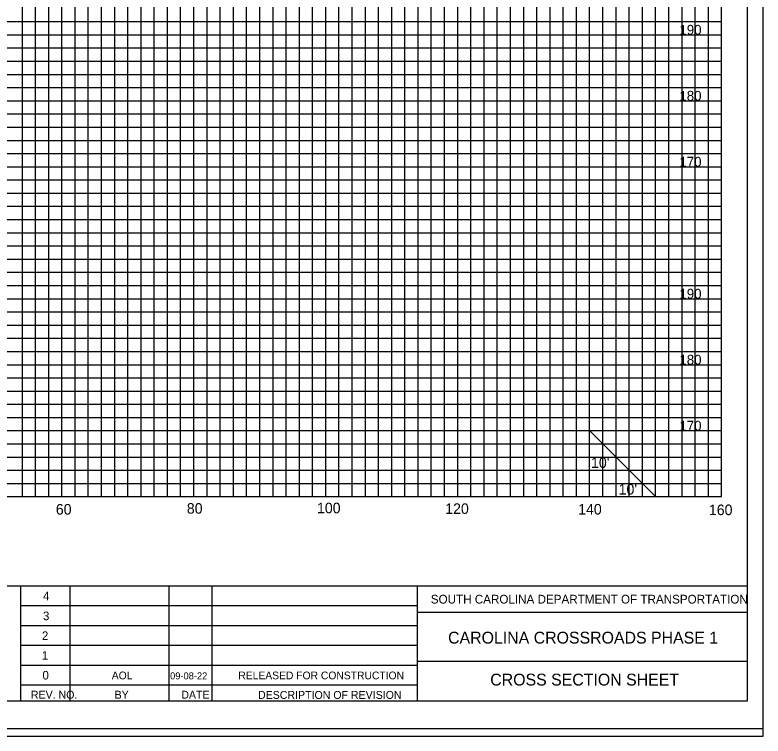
# Model space of a CAD drawing. Extents: x 967 to 1623, y 964 to 7064.
# Drawn here: x 1212.9 to 1326.3, y 963.7 to 1073 of the extents above; entities that cross this region are included whole.
import ezdxf

# ---------------------------------------------------------------- set-up
doc = ezdxf.new("R2010")
doc.units = 0
for name, color, linetype in [('Default', 7, 'Continuous'), ('RD_SHT_Bndy', 7, 'Continuous'), ('RD_SHT_IplotShp', 7, 'Continuous'), ('RD_SHT_Misc1', 7, 'Continuous'), ('RD_SHT_MjGrid', 7, 'Continuous'), ('RD_SHT_MnGrid', 7, 'Continuous'), ('RD_SHT_TX', 7, 'Continuous'), ('RD_Sketch1', 7, 'Continuous')]:
    doc.layers.add(name, color=color, linetype=linetype)

msp = doc.modelspace()

# ---------------------------------------------------------------- linework, layer by layer
at = {"layer": 'RD_SHT_Bndy'}
for p, q in [((1323.89, 1178.46), (1323.89, 968.98)), ((996.11, 986.49), (1323.89, 986.49)), ((1213.76, 968.94), (1213.76, 986.49)), ((1221.26, 968.95), (1221.26, 986.48)), ((1236.26, 968.95), (1236.26, 986.48)), ((1242.76, 968.95), (1242.76, 986.48)), ((1273.88, 968.98), (1273.88, 986.49)), ((1213.76, 983.48), (1273.88, 983.48)), ((1323.93, 982.43), (1273.88, 982.43)), ((1213.76, 980.48), (1273.88, 980.48)), ((1213.76, 977.48), (1273.88, 977.48)), ((1213.76, 974.48), (1273.88, 974.48)), ((1323.89, 975.04), (1273.88, 975.04)), ((1213.76, 971.48), (1273.88, 971.48)), ((1323.89, 968.98), (996.11, 968.98))]:
    msp.add_line(p, q, dxfattribs=at)
at = {"layer": 'RD_SHT_IplotShp'}
for points in [[(967.41, 963.72), (1326.28, 963.72), (1326.28, 1183.72), (967.41, 1183.72)], [(988.52, 964.84), (1326.28, 964.84), (1326.28, 1182.6), (988.52, 1182.6)]]:
    msp.add_lwpolyline(points, close=True, dxfattribs=at)
at = {"layer": 'RD_SHT_MjGrid'}
for p, q in [((1220, 1000), (1220, 1170)), ((1230, 1000), (1230, 1170)), ((1240, 1000), (1240, 1170)), ((1250, 1000), (1250, 1170)), ((1260, 1000), (1260, 1170)), ((1270, 1000), (1270, 1170)), ((1280, 1000), (1280, 1170)), ((1290, 1000), (1290, 1170)), ((1300, 1000), (1300, 1170)), ((1310, 1000), (1310, 1170)), ((1320, 1000), (1320, 1170)), ((1000, 1070), (1320, 1070)), ((1000, 1060), (1320, 1060)), ((1000, 1050), (1320, 1050)), ((1000, 1040), (1320, 1040)), ((1000, 1030), (1320, 1030)), ((1000, 1020), (1320, 1020)), ((1000, 1010), (1320, 1010)), ((1000, 1000), (1320, 1000))]:
    msp.add_line(p, q, dxfattribs=at)
at = {"layer": 'RD_SHT_MnGrid'}
for p, q in [((1214, 1000), (1214, 1170)), ((1216, 1000), (1216, 1170)), ((1218, 1000), (1218, 1170)), ((1222, 1000), (1222, 1170)), ((1224, 1000), (1224, 1170)), ((1226, 1000), (1226, 1170)), ((1228, 1000), (1228, 1170)), ((1232, 1000), (1232, 1170)), ((1234, 1000), (1234, 1170)), ((1236, 1000), (1236, 1170)), ((1238, 1000), (1238, 1170)), ((1242, 1000), (1242, 1170)), ((1244, 1000), (1244, 1170)), ((1246, 1000), (1246, 1170)), ((1248, 1000), (1248, 1170)), ((1252, 1000), (1252, 1170)), ((1254, 1000), (1254, 1170)), ((1256, 1000), (1256, 1170)), ((1258, 1000), (1258, 1170)), ((1262, 1000), (1262, 1170)), ((1264, 1000), (1264, 1170)), ((1266, 1000), (1266, 1170)), ((1268, 1000), (1268, 1170)), ((1272, 1000), (1272, 1170)), ((1274, 1000), (1274, 1170)), ((1276, 1000), (1276, 1170)), ((1278, 1000), (1278, 1170)), ((1282, 1000), (1282, 1170)), ((1284, 1000), (1284, 1170)), ((1286, 1000), (1286, 1170)), ((1288, 1000), (1288, 1170)), ((1292, 1000), (1292, 1170)), ((1294, 1000), (1294, 1170)), ((1296, 1000), (1296, 1170)), ((1298, 1000), (1298, 1170)), ((1302, 1000), (1302, 1170)), ((1304, 1000), (1304, 1170)), ((1306, 1000), (1306, 1170)), ((1308, 1000), (1308, 1170)), ((1312, 1000), (1312, 1170)), ((1314, 1000), (1314, 1170)), ((1316, 1000), (1316, 1170)), ((1318, 1000), (1318, 1170)), ((1000, 1072), (1320, 1072)), ((1000, 1068), (1320, 1068)), ((1000, 1066), (1320, 1066)), ((1000, 1064), (1320, 1064)), ((1000, 1062), (1320, 1062)), ((1000, 1058), (1320, 1058)), ((1000, 1056), (1320, 1056)), ((1000, 1054), (1320, 1054)), ((1000, 1052), (1320, 1052)), ((1000, 1048), (1320, 1048)), ((1000, 1046), (1320, 1046)), ((1000, 1044), (1320, 1044)), ((1000, 1042), (1320, 1042)), ((1000, 1038), (1320, 1038)), ((1000, 1036), (1320, 1036)), ((1000, 1034), (1320, 1034)), ((1000, 1032), (1320, 1032)), ((1000, 1028), (1320, 1028)), ((1000, 1026), (1320, 1026)), ((1000, 1024), (1320, 1024)), ((1000, 1022), (1320, 1022)), ((1000, 1018), (1320, 1018)), ((1000, 1016), (1320, 1016)), ((1000, 1014), (1320, 1014)), ((1000, 1012), (1320, 1012)), ((1000, 1008), (1320, 1008)), ((1000, 1006), (1320, 1006)), ((1000, 1004), (1320, 1004)), ((1000, 1002), (1320, 1002))]:
    msp.add_line(p, q, dxfattribs=at)
at = {"layer": 'RD_SHT_TX'}
msp.add_line((1300, 1010), (1310, 1000), dxfattribs=at)
at = {"layer": 'RD_Sketch1'}
msp.add_lwpolyline([(967.41, 963.72), (1326.28, 963.72), (1326.28, 1183.72), (967.41, 1183.72)], close=True, dxfattribs=at)

# ---------------------------------------------------------------- texts
at = {"layer": 'Default'}
for s, p in [('190', (1313.61, 1070)), ('180', (1313.61, 1060)), ('170', (1313.61, 1050)), ('190', (1313.61, 1030)), ('180', (1313.61, 1020)), ('170', (1313.61, 1010))]:
    msp.add_text(s, height=1.5, dxfattribs=at).set_placement(p)
at = {"layer": 'RD_SHT_Misc1'}
for s, height, p in [('AOL', 1.17, (1227.56, 972.32)), ('09-08-22', 1.053, (1236.4, 972.31)), ('RELEASED FOR CONSTRUCTION', 1.17, (1246.74, 972.32))]:
    msp.add_text(s, height=height, dxfattribs=at).set_placement(p)
at = {"layer": 'RD_SHT_TX'}
for s, height, p in [("10'", 1.6, (1300.21, 1004.36)), ("10'", 1.6, (1304.4, 1000.32)), ('100', 1.6, (1258.67, 997.48)), ('60', 1.6, (1219.08, 997.28)), ('80', 1.6, (1238.94, 997.42)), ('120', 1.6, (1278.11, 997.38)), ('140', 1.6, (1298.26, 997.29)), ('160', 1.6, (1318.08, 997.2)), ('4', 1.3, (1217.13, 984.28)), ('SOUTH CAROLINA DEPARTMENT OF TRANSPORTATION', 1.32, (1275.92, 983.8)), ('3', 1.3, (1217.13, 981.28)), ('2', 1.3, (1216.97, 978.28)), ('1', 1.3, (1216.97, 975.28)), ('0', 1.3, (1217.05, 972.28)), ('REV. NO.', 1.2, (1215.3, 969.38)), ('BY', 1.2, (1227.99, 969.38)), ('DATE', 1.2, (1238.1, 969.38)), ('DESCRIPTION OF REVISION', 1.2, (1249.73, 969.35))]:
    msp.add_text(s, height=height, dxfattribs=at).set_placement(p)
for s, p in [('CAROLINA CROSSROADS PHASE 1', (1278.54, 977.73)), ('CROSS SECTION SHEET', (1284.93, 971.37))]:
    msp.add_text(s, height=1.8, rotation=0, dxfattribs=at).set_placement(p)

doc.saveas('drawing.dxf')
